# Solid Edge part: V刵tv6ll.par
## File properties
Author: KULL
Template: Iso Metric Part.par
Last saved by: KULL
Revision: 43
Application: Solid Edge
Density: 6920,000 kg/m^3
Accuracy: 0,990
Material: Iron, grey cast type 60
Face Style: Gray
Fill Style: ANSI31(Iron)
Virtual Style: ANSI31(Iron)
Categorization: Metals\Iron
LibraryName: Materials
Coef. of Thermal Exp: 1.1e-05
Thermal Conductivity: 48.0
Specific Heat: 544.0
Modulus of Elasticity: 158579411000.0
Poisson's Ratio: 0.29
Yield Stress: 275790291.72673446
Ultimate Stress: 413685437.59010166
Elongation: 0.0
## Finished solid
Body 1: solid body, 372 faces, 762 edges, 400 vertices.
  Faces by surface: cylinder 164, plane 74, blend 70, torus 64
  Edges by curve: circle 360, line 260, ellipse 140, intersection 2
Bounding box of the edges (mm; curved faces can reach further): 133.725 x 22.000 x 22.000, from (-65.4552, -11, 27.6638) to (68.2698, 11, 49.6638).
Cylindrical faces by radius (mm): R0.2 x40, R0.4 x1, R0.6 x40, R1.2 x20, R1.5 x5, R2.7 x4, R3 x22, R5 x2, R6 x20, R11 x10
Toroidal faces (ring radius, tube radius in mm): R1 r0.2 x20, R2.8 r0.2 x12, R4 r1 x2, R6.2 r0.2 x20, R10.8 r0.2 x10
Planar faces by outward normal: +x 12, -x 12, oblique 50
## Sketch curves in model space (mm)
circle centre (53.1423, 0, 38.6638) radius 3
line (-36, 0, 38.6638) -> (-36, -5.1423, 44.7922)
line (-48, 0, 38.6638) -> (-48, 12.4304, 23.8499)
line (-48, 0, 38.6638) -> (-48, -12.4304, 23.8499)
line (-48, 0, 38.6638) -> (-48, -35.0326, 80.4141)
line (-48, 0, 38.6638) -> (-48, 35.0326, 80.4141)
circle centre (-48, 0, 38.6638) radius 4
circle centre (48, 0, 38.6638) radius 4
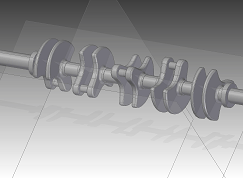
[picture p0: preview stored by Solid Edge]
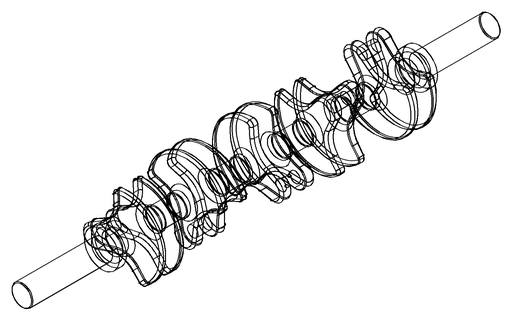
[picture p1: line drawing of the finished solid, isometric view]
